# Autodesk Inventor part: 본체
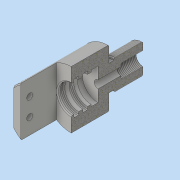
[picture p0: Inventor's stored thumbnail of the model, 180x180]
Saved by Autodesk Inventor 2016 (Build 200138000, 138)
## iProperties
Created: 2019-02
Part Number: 본체
Material: 일반
Document SubType Name: Modeling
Designer: 3sil_cad0123
Density: 1 g/cm^3
Appearance: 기본값
Author: 3sil_cad0123
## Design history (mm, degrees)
sketch "스케치1"
  geometry: C1 r 29 at (0, 0); 1 further point
  constraints: 1 centre point, 1 coincident
  dimensions: "d0" = 58 diameter of C1
extrude "돌출1" new body sketch "스케치1" distance "d1" = 74; taper "d2" = 0 deg
sketch "스케치2"
  geometry: C1 r 29 at (0, 0) reference; C2 r 13 at (0, 0)
  constraints: 1 centre point, 1 coincident
  dimensions: "d3" = 26 diameter of C2
extrude "돌출2" join sketch "스케치2" distance "d4" = 5; taper "d5" = 0 deg
sketch "스케치3"
  geometry: C1 r 13 at (0, 0) reference; C2 r 15 at (0, 0)
  constraints: 1 centre point, 1 coincident
  dimensions: "d6" = 30 diameter of C2
extrude "돌출3" join sketch "스케치3" distance "d7" = 29; taper "d8" = 0 deg
feature "스레드1" dims "d9" = 10, "d10" = 0
sketch "스케치4"
  geometry: C1 r 15 at (0, 0) reference; C2 r 7 at (0, 0)
  constraints: 1 centre point, 1 coincident
  dimensions: "d11" = 14 diameter of C2
extrude "돌출4" cut sketch "스케치4" distance "d12" = 18; taper "d13" = 0 deg
feature "스레드2" dims "d14" = 10, "d15" = 0
sketch "스케치6"
  geometry: C1 r 7 at (0, 0) reference; 1 further point
  constraints: 1 coincident
hole "구멍1" sketch "스케치6" at (0, 0) diameter "d16" = 8; stored, may be unused: countersink angle "d20" = 90 deg, drill point angle "d22" = 118 deg; dims "d17" = 6, "d18" = 14, "d19" = 4, "d21" = 8
node "작업 평면1"
sketch "스케치7"
  geometry: L1 (15, 36)-(-15, 36); L2 (-15, 36)-(-15, -36); L3 (-15, -36)-(15, -36); L4 (15, -36)-(15, 36); L5 (15, 36)-(-15, -36); L6 (-15, 36)-(15, -36); L7 (-29, 0)-(-29, -74) reference; L8 (-29, -16)-(-22, -16); L9 (-22, -16)-(-22, 0); L10 (-22, 0)-(-29, 0); L11 (-29, 0)-(-29, -16); L12 (29, 0)-(29, -74) reference; L13 (29, 0)-(22, 0); L14 (22, 0)-(22, -16); L15 (22, -16)-(29, -16); L16 (29, -16)-(29, 0); L17 (-29, 0)-(29, 0) reference; 1 further point
  constraints: 28 end point, 6 parallel, 3 horizontal, 3 perpendicular, 2 midpoint, 2 point on line
  dimensions: "d23" = 30 distance of L3.end L2.end; "d24" = 72 distance of L2.end L1.end; "d27" = 16 distance of L8.end L9.end; "d28" = 7 distance of L9.end L10.end; "d29" = 16 distance of L15.end L13.start; "d30" = 7 distance of L13.start L13.end; "d31" = 0 distance from line of L17 L13.end; "d32" = 0 distance between parallel lines of L10 L17
extrude "돌출5" cut sketch "스케치7" stored distance "d25" = 18; taper "d26" = 0 deg
sketch "스케치8"
  geometry: L1 (-129.6, 18.894)-(21.6, 18.894) reference; 3 further points
  constraints: 1 symmetric about line
  dimensions: "d33" = 18 distance of point (-9, 27.894) point (-9, 9.894); "d34" = 9 horizontal distance of point (0, 18.894) point (-9, 27.894)
hole "구멍2" sketch "스케치8" at (-9, 9.894), (-9, 27.894) diameter "d35" = 6; stored, may be unused: countersink angle "d39" = 90 deg, drill point angle "d41" = 118 deg; dims "d36" = 6, "d37" = 14, "d38" = 4, "d40" = 8
sketch "스케치9"
  geometry: L1 (0, -129.6)-(0, 21.6) reference; L2 (-15, -79)-(-13, -79) reference; L3 (-13, -79)-(-13, -74) reference; L4 (-13, -74)-(-29, -74) reference; L5 (-29, -74)-(-29, -36) reference; L6 (-29, -36)-(-4, -36) reference; L7 (-4, -36)-(-4, -86) reference; L8 (-4, -86)-(-7, -86) reference; L9 (-7, -86)-(-7, -108) reference; L10 (-7, -108)-(-15, -108) reference; L11 (-15, -108)-(-15, -79) reference; L12 (13, -79)-(15, -79) reference; L13 (15, -79)-(15, -108) reference; L14 (15, -108)-(7, -108) reference; L15 (7, -108)-(7, -86) reference; L16 (7, -86)-(4, -86) reference; L17 (4, -86)-(4, -36) reference; L18 (4, -36)-(29, -36) reference; L19 (29, -36)-(29, -74) reference; L20 (29, -74)-(13, -74) reference; L21 (13, -74)-(13, -79) reference; L22 (0, -63)-(-49, -63); L23 (0, -63)-(-16, -63); L24 (-16, -63)-(-16, -56); L25 (-16, -56)-(-14, -56); L26 (-14, -56)-(-14, -52.35); L27 (-14, -52.35)-(-17, -52.35); L28 (-17, -52.35)-(-17, -47.65); L29 (-17, -47.65)-(-14, -47.65); L30 (-14, -47.65)-(-14, -43.35); L31 (-14, -43.35)-(-17, -43.35); L32 (-17, -43.35)-(-17, -38.65); L33 (-17, -38.65)-(-14, -38.65); L34 (-14, -38.65)-(-14, -36); L35 (-14, -36)-(0, -36); L36 (-24.819, -36)-(24.819, -36) reference; L37 (0, -63)-(0, -36); 3 further points
  constraints: 30 end point, 9 perpendicular, 7 point on line, 3 midpoint, 1 collinear, 1 horizontal
  dimensions: "d42" = 27 distance between parallel lines of L6 L22; "d43" = 16 distance of L22.start L23.end; "d44" = 7 distance of L23.end L24.end; "d45" = 4.7 distance between parallel lines of L27 L29; "d46" = 4.7 distance between parallel lines of L33 L31; "d47" = 14 distance between parallel lines of L1 L34; "d48" = 14 distance between parallel lines of L1 L26; "d49" = 5 distance from line of L6 point (-17, -41); "d50" = 9 distance of point (-17, -41) point (-17, -50); "d51" = 17 distance from line of L1 point (-17, -41)
revolve "회전1" sketch "스케치9" stored, may be unused: angle "d52" = 90 deg
node "작업 평면3"
  node "작업 평면2"
sketch "스케치10"
  geometry: L1 (5, -29)-(-5, -29); L2 (-5, -29)-(-5, -69); L3 (-5, -69)-(5, -69); L4 (5, -69)-(5, -29); L5 (5, -29)-(-5, -69); L6 (-5, -29)-(5, -69); L7 (-24.819, 0)-(-18.894, 0) reference; L8 (-24.819, -36)-(-24.819, 0) reference; L9 (-29, -74)-(29, -74) reference; L10 (18.894, 0)-(18.894, -16) reference; L11 (18.894, -16)-(-18.894, -16) reference; L12 (-18.894, -16)-(-18.894, 0) reference; L13 (-18.894, 0)-(-24.819, 0) reference; L14 (-24.819, 0)-(-24.819, -36) reference; L15 (-24.819, -36)-(-24.819, -36) reference; L16 (-24.819, -36)-(-24.819, 0) reference; L17 (-24.819, 0)-(-18.894, 0) reference; L18 (-18.894, 0)-(-18.894, -16) reference; L19 (-18.894, -16)-(18.894, -16) reference; L20 (18.894, -16)-(18.894, 0) reference; L21 (18.894, 0)-(24.819, 0) reference; L22 (24.819, 0)-(24.819, -36) reference; L23 (24.819, -36)-(24.819, -36) reference; L24 (24.819, -36)-(24.819, 0) reference; L25 (24.819, 0)-(18.894, 0) reference; 2 further points
  constraints: 12 end point, 2 midpoint, 2 parallel, 1 horizontal, 1 perpendicular
  dimensions: "d54" = 20 distance from line of L1 point (0, -49); "d55" = 0 horizontal distance of point (0, 0) point (0, -49); "d56" = 10 distance between parallel lines of L4 L2; "d57" = 5 distance between parallel lines of L9 L3
extrude "돌출6" join sketch "스케치10" stored distance "d58" = 18; taper "d59" = 0 deg
node "작업 평면4"
sketch "스케치11"
  geometry: L1 (-52.35, 17)-(-52.35, -17) reference; L2 (-29, 5)-(-29, -5) reference; L3 (-69, 5)-(-29, 5) reference; L4 (-69, -5)-(-69, 5) reference; L5 (-29, -5)-(-69, -5) reference; 2 further points
  constraints: 1 other
  dimensions: "d61" = 20 distance from line of L2 point (-49, 0); "d62" = 5 distance from line of L5 point (-49, 0)
feature "엠보싱1" sketch "스케치11" dims "d63" = 0.5, "d64" = 0
chamfer "모따기1" distance "d65" = 1; stored, may be unused: second distance "d66" = 2, angle "d67" = 45 deg
chamfer "모따기2" distance "d68" = 1; stored, may be unused: second distance "d69" = 2, angle "d70" = 45 deg
chamfer "모따기3" distance "d71" = 1; stored, may be unused: second distance "d72" = 2, angle "d73" = 45 deg
chamfer "모따기4" distance "d74" = 1; stored, may be unused: second distance "d75" = 2, angle "d76" = 45 deg
fillet "모깎기1" dims "d80" = 0.8
chamfer "모따기6" distance "d81" = 1; stored, may be unused: second distance "d82" = 2, angle "d83" = 45 deg
node "솔리드1"
node "투영된 루프1"
node "투영된 루프2"
node "절단 모서리 투영1"
other parameters: "d53" = -59
